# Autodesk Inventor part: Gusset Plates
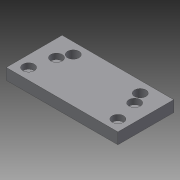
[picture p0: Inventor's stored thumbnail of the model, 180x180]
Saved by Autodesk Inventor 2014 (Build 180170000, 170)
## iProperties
Created: 2013-11
Part Number: Gusset Plates
Material: Generic
Document SubType Name: Modeling
Designer: 603839
Density: 1 g/cm^3
Appearance: Default
Mass: 95.3765 g
Surface Area: 228.727 cm^2
Volume: 95.3765 cm^3
Author: 603839
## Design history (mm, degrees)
sketch "Sketch2"
  geometry: L1 (-6.35, 31.75)-(-6.35, -31.75); L2 (-6.35, -31.75)-(6.35, -31.75); L3 (6.35, -31.75)-(6.35, 31.75); L4 (6.35, 31.75)-(-6.35, 31.75); L5 (-6.35, 31.75)-(6.35, -31.75); L6 (-6.35, -31.75)-(6.35, 31.75); 1 further point
  constraints: 12 end point, 2 midpoint, 2 parallel, 1 perpendicular, 1 vertical
  dimensions: "d0" = 63.5 distance of L1.start L1.end; "d1" = 12.7 distance of L2.end L1.end
extrude "Extrusion1" new body sketch "Sketch2" distance "d2" = 127; taper "d3" = 0 deg
hole "Hole1" diameter "d6" = 12.954; stored, may be unused: countersink angle "d10" = 82 deg, drill point angle "d12" = 0 deg; dims "d4" = 12.7, "d5" = 12.7, "d7" = 19.05, "d8" = 9.525, "d9" = 6.35, "d11" = 6.35
hole "Hole2" diameter "d15" = 12.954; stored, may be unused: countersink angle "d19" = 82 deg, drill point angle "d21" = 0 deg; dims "d13" = 19.05, "d14" = 25.4, "d16" = 19.05, "d17" = 9.525, "d18" = 6.35, "d20" = 6.35
hole "Hole3" diameter "d24" = 12.954; stored, may be unused: countersink angle "d28" = 82 deg, drill point angle "d30" = 0 deg; dims "d22" = 12.7, "d23" = 12.7, "d25" = 19.05, "d26" = 9.525, "d27" = 6.35, "d29" = 6.35
hole "Hole4" diameter "d33" = 12.954; stored, may be unused: countersink angle "d37" = 82 deg, drill point angle "d39" = 0 deg; dims "d31" = 25.4, "d32" = 19.05, "d34" = 19.05, "d35" = 9.525, "d36" = 6.35, "d38" = 6.35
hole "Hole5" diameter "d42" = 12.954; stored, may be unused: countersink angle "d46" = 82 deg, drill point angle "d48" = 0 deg; dims "d40" = 12.7, "d41" = 25.4, "d43" = 19.05, "d44" = 9.525, "d45" = 6.35, "d47" = 12.7
hole "Hole6" diameter "d51" = 12.954; stored, may be unused: countersink angle "d55" = 82 deg, drill point angle "d57" = 0 deg; dims "d49" = 12.7, "d50" = 25.4, "d52" = 19.05, "d53" = 9.525, "d54" = 6.35, "d56" = 12.7
sketch "Sketch3"
  geometry: C1 r 1.905 at (25.4, 22.225); C2 r 1.905 at (25.4, 3.175); C3 r 1.905 at (34.925, 12.7); C4 r 1.905 at (15.875, 12.7); 1 further point
  constraints: 4 centre point
  dimensions: "d59" = 3.81 diameter of C1; "d60" = 3.81 diameter of C2; "d61" = 3.81 diameter of C3; "d62" = 3.81 diameter of C4
extrude "Extrusion2" cut sketch "Sketch3" distance "d63" = 3.81; taper "d64" = 0 deg
sketch "Sketch4"
  geometry: C1 r 6.477 at (101.6, 12.7) reference; C2 r 1.905 at (101.6, 22.225); C3 r 1.905 at (92.075, 12.7); C4 r 1.905 at (101.6, 3.175); C5 r 1.905 at (111.125, 12.7); A1 r 9.525 centre (101.6, 12.7) between (101.6, 22.225) and (92.075, 12.7); 1 further point
  constraints: 5 centre point, 4 point on circle, 1 coincident
  dimensions: "d65" = 19.05 diameter of A1; "d66" = 3.81 diameter of C2; "d67" = 3.81 diameter of C3; "d68" = 3.81 diameter of C4; "d69" = 3.81 diameter of C5
extrude "Extrusion3" cut sketch "Sketch4" distance "d70" = 3.81; taper "d71" = 0 deg
body "Solid1"
